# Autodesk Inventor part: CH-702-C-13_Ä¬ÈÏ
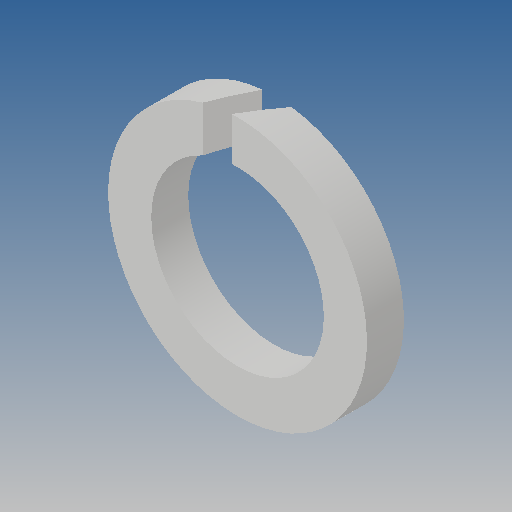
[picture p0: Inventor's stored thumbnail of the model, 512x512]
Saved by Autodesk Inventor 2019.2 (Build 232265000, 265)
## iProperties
Created: 2010-06
Part Number: CH-702-C-13_Ä¬ÈÏ
Material: Ogólny
Document SubType Name: Modeling
Designer: CADENGINEERING4
Density: 1 g/cm^3
Appearance: Domyślna
Author: CADENGINEERING4
Revision Number: ÈÎºÎ
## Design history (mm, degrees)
feature "NONE"
node "Bryła1"
